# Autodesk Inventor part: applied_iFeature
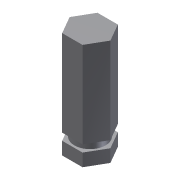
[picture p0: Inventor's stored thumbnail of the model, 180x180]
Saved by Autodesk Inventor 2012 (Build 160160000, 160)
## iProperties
Created: 2011-07
Part Number: applied_iFeature
Material: Default
Document SubType Name: Modeling
Designer: CadCim
Density: 1 g/cm^3
Author: CadCim
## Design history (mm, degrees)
sketch "Sketch1"
  geometry: L1 (14.434, 25)-(28.868, 0); L2 (28.868, 0)-(14.434, -25); L3 (14.434, -25)-(-14.434, -25); L4 (-14.434, -25)-(-28.868, 0); L5 (-28.868, 0)-(-14.434, 25); L6 (-14.434, 25)-(14.434, 25); 2 further points
  constraints: 12 end point, 1 coincident, 13 other
  dimensions: "d1" = 50 distance of L2.end L1.start
extrude "Extrusion1" new body sketch "Sketch1" distance "d2" = 150; taper "d3" = 0 deg
feature "iFeature1:1"
body "Solid1"
